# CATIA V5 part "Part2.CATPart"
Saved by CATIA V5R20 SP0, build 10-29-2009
Part number: Part2
Bounding box of the stored display mesh (mm): x 3 to 20, y -7 to 63.99, z 108.003 to 121.997
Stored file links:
  C:\Users\Ehsan Fathi\Desktop\Part2.CATPart
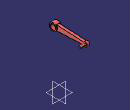
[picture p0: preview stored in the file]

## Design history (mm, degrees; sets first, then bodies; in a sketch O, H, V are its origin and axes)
Body1 (main body)
  DatumSurface1
  DatumCurve1
  Sketch1 on face of DatumSurface1, origin (5, 0, 0), H (0, 1, 0), V (0, 0, 1)
    projected circle E1 centre (0, 115) radius 5 from edge of DatumCurve1
    arc A1 centre (0, 115) radius 7 from (4.899, 120) to (4.899, 110) ccw
    point P1 (0, 115)
    circle A2 centre (60, 115) radius 2
    point P2 (60, 115)
    arc A3 centre (60, 115) radius 4 from (56.8775, 112.5) to (56.8775, 117.5) ccw
    line L1 (4.899, 120) -> (56.8775, 117.5)
    point P3 (4.899, 120)
    point P4 (56.8775, 117.5)
    axis line L2 (0, 115) -> (60, 115)
    point P5 (60, 115)
    point P6 (56.8775, 112.5)
    point P7 (4.899, 110)
    line L3 (4.899, 110) -> (56.8775, 112.5)
    arc A4 centre (60, 115) radius 4 from (56.8775, 117.5) to (56.8775, 112.5) ccw
    arc A5 centre (0, 115) radius 7 from (4.899, 110) to (4.899, 120) ccw
    radius A1 = 7
    radius A3 = 4
    distance P1 P2 = 60
    distance P3 P1 V = 5
    distance P4 P2 V = 2.5
    concentricity: P1 E1, P5 A2
    horizontal: L2 H
    symmetry: P4 P6 L2, P3 P7 L2, L1 L3 L2
    coincidence: A3 A4, A1 A5
  MultiPad1: profile Sketch1, domains (length 5; length 5; length 7 / length 2; length 15; length 0)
